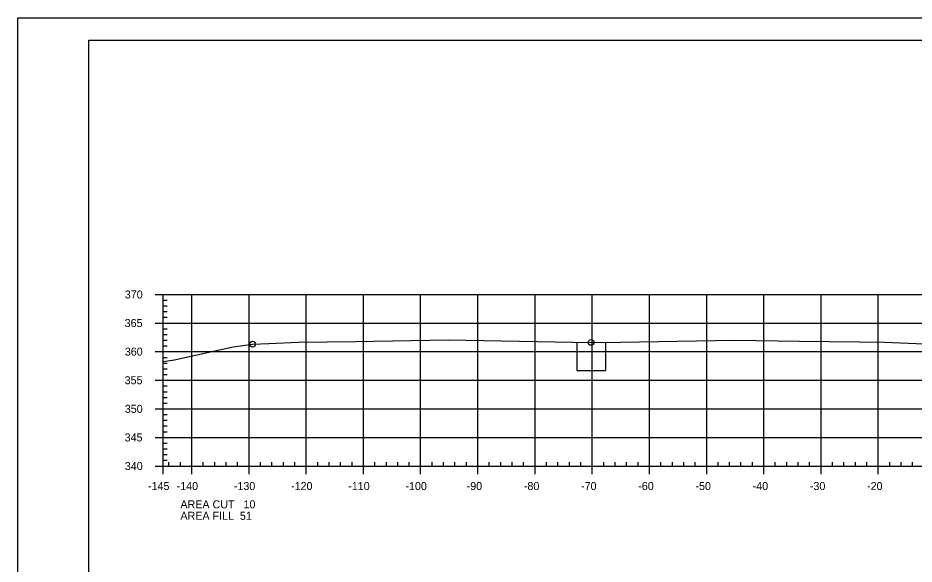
# Model space of a CAD drawing. Extents: x 1359801 to 1362404, y 372415 to 374228.
# Drawn here: x 1360417.1 to 1360573.8, y 373279.1 to 373374.6 of the extents above; entities that cross this region are included whole.
import ezdxf

# ---------------------------------------------------------------- set-up
doc = ezdxf.new("R2010")
doc.units = 0
for name, color, linetype in [('S_DRG_PT_SYM', 7, 'Continuous'), ('S_MAILBOX', 7, 'Continuous'), ('S_PRIMARY_CTL', 7, 'Continuous'), ('S_SHOULDER', 7, 'Continuous'), ('S_UTILITY_POLE_ANNOT', 7, 'Continuous'), ('S_UTL_PT_SYM', 7, 'Continuous'), ('S_WATER_UTILITIES', 7, 'Continuous')]:
    doc.layers.add(name, color=color, linetype=linetype)

msp = doc.modelspace()

# ---------------------------------------------------------------- linework, layer by layer
at = {"layer": 'S_DRG_PT_SYM'}
msp.add_lwpolyline([(1360442.53, 373314.56), (1360444.48, 373314.85), (1360449.99, 373316.06), (1360454.74, 373317.08), (1360456.47, 373317.32), (1360458.15, 373317.57), (1360460.98, 373317.68), (1360466.15, 373317.9), (1360476.17, 373318.06), (1360492.36, 373318.32), (1360514.12, 373317.93), (1360519.42, 373317.83), (1360522.47, 373317.89), (1360542.41, 373318.26), (1360553.77, 373318.1), (1360564.27, 373317.95), (1360568.61, 373317.9), (1360575.57, 373317.63)], dxfattribs=at)
at = {"layer": 'S_MAILBOX'}
for p, q in [((1360442.53, 373326.26), (1360732.53, 373326.26)), ((1360442.53, 373296.26), (1360442.53, 373326.26)), ((1360447.53, 373296.26), (1360447.53, 373326.26)), ((1360457.53, 373296.26), (1360457.53, 373326.26)), ((1360467.53, 373296.26), (1360467.53, 373326.26)), ((1360477.53, 373296.26), (1360477.53, 373326.26)), ((1360487.53, 373296.26), (1360487.53, 373326.26)), ((1360497.53, 373296.26), (1360497.53, 373326.26)), ((1360507.53, 373296.26), (1360507.53, 373326.26)), ((1360517.53, 373296.26), (1360517.53, 373326.26)), ((1360527.53, 373296.26), (1360527.53, 373326.26)), ((1360537.53, 373296.26), (1360537.53, 373326.26)), ((1360547.53, 373296.26), (1360547.53, 373326.26)), ((1360557.53, 373296.26), (1360557.53, 373326.26)), ((1360567.53, 373296.26), (1360567.53, 373326.26)), ((1360442.53, 373321.26), (1360732.53, 373321.26)), ((1360442.53, 373316.26), (1360732.53, 373316.26)), ((1360442.53, 373311.26), (1360732.53, 373311.26)), ((1360442.53, 373306.26), (1360732.53, 373306.26)), ((1360442.53, 373301.26), (1360732.53, 373301.26)), ((1360442.53, 373296.26), (1360732.53, 373296.26))]:
    msp.add_line(p, q, dxfattribs=at)
at = {"layer": 'S_SHOULDER'}
msp.add_line((1360417.13, 373374.61), (1360750.46, 373374.61), dxfattribs=at)
for points in [[(1360417.12, 373374.61), (1360750.46, 373374.61), (1360750.46, 373161.28), (1360417.12, 373161.28)], [(1360663.45, 373370.72), (1360663.45, 373360.84), (1360699.18, 373360.84), (1360699.18, 373357.92), (1360722.38, 373357.92), (1360722.38, 373333.59), (1360745.71, 373333.59), (1360745.71, 373165.26), (1360429.53, 373165.26), (1360429.53, 373370.72)]]:
    msp.add_lwpolyline(points, close=True, dxfattribs=at)
for centre in [(1360458.15, 373317.57), (1360517.32, 373317.87)]:
    msp.add_circle(centre, 0.5, dxfattribs=at)
at = {"layer": 'S_UTILITY_POLE_ANNOT'}
for p, q in [((1360514.82, 373317.87), (1360514.82, 373312.95)), ((1360519.82, 373317.87), (1360519.82, 373312.95)), ((1360514.82, 373312.95), (1360519.82, 373312.95))]:
    msp.add_line(p, q, dxfattribs=at)
at = {"layer": 'S_UTL_PT_SYM'}
for p, q in [((1360429.53, 373370.72), (1360745.71, 373370.72)), ((1360429.53, 373165.26), (1360429.53, 373370.72))]:
    msp.add_line(p, q, dxfattribs=at)
at = {"layer": 'S_WATER_UTILITIES'}
for p, q in [((1360441.13, 373326.26), (1360442.53, 373326.26)), ((1360442.53, 373296.26), (1360442.53, 373326.26)), ((1360442.53, 373325.26), (1360443.23, 373325.26)), ((1360442.53, 373324.26), (1360443.23, 373324.26)), ((1360442.53, 373323.26), (1360443.23, 373323.26)), ((1360442.53, 373322.26), (1360443.23, 373322.26)), ((1360441.13, 373321.26), (1360442.53, 373321.26)), ((1360442.53, 373320.26), (1360443.23, 373320.26)), ((1360442.53, 373319.26), (1360443.23, 373319.26)), ((1360442.53, 373318.26), (1360443.23, 373318.26)), ((1360442.53, 373317.26), (1360443.23, 373317.26)), ((1360441.13, 373316.26), (1360442.53, 373316.26)), ((1360442.53, 373315.26), (1360443.23, 373315.26)), ((1360442.53, 373314.26), (1360443.23, 373314.26)), ((1360442.53, 373313.26), (1360443.23, 373313.26)), ((1360441.13, 373311.26), (1360442.53, 373311.26)), ((1360442.53, 373312.26), (1360443.23, 373312.26)), ((1360442.53, 373310.26), (1360443.23, 373310.26)), ((1360442.53, 373309.26), (1360443.23, 373309.26)), ((1360442.53, 373308.26), (1360443.23, 373308.26)), ((1360441.13, 373306.26), (1360442.53, 373306.26)), ((1360442.53, 373307.26), (1360443.23, 373307.26)), ((1360442.53, 373305.26), (1360443.23, 373305.26)), ((1360442.53, 373304.26), (1360443.23, 373304.26)), ((1360442.53, 373303.26), (1360443.23, 373303.26)), ((1360442.53, 373302.26), (1360443.23, 373302.26)), ((1360441.13, 373301.26), (1360442.53, 373301.26)), ((1360442.53, 373300.26), (1360443.23, 373300.26)), ((1360442.53, 373299.26), (1360443.23, 373299.26)), ((1360442.53, 373298.26), (1360443.23, 373298.26)), ((1360442.53, 373297.26), (1360443.23, 373297.26)), ((1360442.53, 373296.26), (1360442.53, 373296.96)), ((1360443.53, 373296.26), (1360443.53, 373296.96)), ((1360445.53, 373296.26), (1360445.53, 373296.96)), ((1360449.53, 373296.26), (1360449.53, 373296.96)), ((1360451.53, 373296.26), (1360451.53, 373296.96)), ((1360453.53, 373296.26), (1360453.53, 373296.96)), ((1360455.53, 373296.26), (1360455.53, 373296.96)), ((1360459.53, 373296.26), (1360459.53, 373296.96)), ((1360461.53, 373296.26), (1360461.53, 373296.96)), ((1360463.53, 373296.26), (1360463.53, 373296.96)), ((1360465.53, 373296.26), (1360465.53, 373296.96)), ((1360469.53, 373296.26), (1360469.53, 373296.96)), ((1360471.53, 373296.26), (1360471.53, 373296.96)), ((1360473.53, 373296.26), (1360473.53, 373296.96)), ((1360475.53, 373296.26), (1360475.53, 373296.96)), ((1360479.53, 373296.26), (1360479.53, 373296.96)), ((1360481.53, 373296.26), (1360481.53, 373296.96)), ((1360483.53, 373296.26), (1360483.53, 373296.96)), ((1360485.53, 373296.26), (1360485.53, 373296.96)), ((1360489.53, 373296.26), (1360489.53, 373296.96)), ((1360491.53, 373296.26), (1360491.53, 373296.96)), ((1360493.53, 373296.26), (1360493.53, 373296.96)), ((1360495.53, 373296.26), (1360495.53, 373296.96)), ((1360499.53, 373296.26), (1360499.53, 373296.96)), ((1360501.53, 373296.26), (1360501.53, 373296.96)), ((1360503.53, 373296.26), (1360503.53, 373296.96)), ((1360505.53, 373296.26), (1360505.53, 373296.96)), ((1360509.53, 373296.26), (1360509.53, 373296.96)), ((1360511.53, 373296.26), (1360511.53, 373296.96)), ((1360513.53, 373296.26), (1360513.53, 373296.96)), ((1360515.53, 373296.26), (1360515.53, 373296.96)), ((1360519.53, 373296.26), (1360519.53, 373296.96)), ((1360521.53, 373296.26), (1360521.53, 373296.96)), ((1360523.53, 373296.26), (1360523.53, 373296.96)), ((1360525.53, 373296.26), (1360525.53, 373296.96)), ((1360529.53, 373296.26), (1360529.53, 373296.96)), ((1360531.53, 373296.26), (1360531.53, 373296.96)), ((1360533.53, 373296.26), (1360533.53, 373296.96)), ((1360535.53, 373296.26), (1360535.53, 373296.96)), ((1360539.53, 373296.26), (1360539.53, 373296.96)), ((1360541.53, 373296.26), (1360541.53, 373296.96)), ((1360543.53, 373296.26), (1360543.53, 373296.96)), ((1360545.53, 373296.26), (1360545.53, 373296.96)), ((1360549.53, 373296.26), (1360549.53, 373296.96)), ((1360551.53, 373296.26), (1360551.53, 373296.96)), ((1360553.53, 373296.26), (1360553.53, 373296.96)), ((1360555.53, 373296.26), (1360555.53, 373296.96)), ((1360559.53, 373296.26), (1360559.53, 373296.96)), ((1360561.53, 373296.26), (1360561.53, 373296.96)), ((1360563.53, 373296.26), (1360563.53, 373296.96)), ((1360565.53, 373296.26), (1360565.53, 373296.96)), ((1360569.53, 373296.26), (1360569.53, 373296.96)), ((1360571.53, 373296.26), (1360571.53, 373296.96)), ((1360573.53, 373296.26), (1360573.53, 373296.96)), ((1360441.13, 373296.26), (1360442.53, 373296.26)), ((1360442.53, 373296.26), (1360732.53, 373296.26)), ((1360442.53, 373294.86), (1360442.53, 373296.26)), ((1360447.53, 373294.86), (1360447.53, 373296.26)), ((1360457.53, 373294.86), (1360457.53, 373296.26)), ((1360467.53, 373294.86), (1360467.53, 373296.26)), ((1360477.53, 373294.86), (1360477.53, 373296.26)), ((1360487.53, 373294.86), (1360487.53, 373296.26)), ((1360497.53, 373294.86), (1360497.53, 373296.26)), ((1360507.53, 373294.86), (1360507.53, 373296.26)), ((1360517.53, 373294.86), (1360517.53, 373296.26)), ((1360527.53, 373294.86), (1360527.53, 373296.26)), ((1360537.53, 373294.86), (1360537.53, 373296.26)), ((1360547.53, 373294.86), (1360547.53, 373296.26)), ((1360557.53, 373294.86), (1360557.53, 373296.26)), ((1360567.53, 373294.86), (1360567.53, 373296.26))]:
    msp.add_line(p, q, dxfattribs=at)

# ---------------------------------------------------------------- texts
at = {"layer": 'S_PRIMARY_CTL'}
for s, p in [('370', (1360435.81, 373325.56)), ('365', (1360435.78, 373320.56)), ('360', (1360435.81, 373315.56)), ('355', (1360435.78, 373310.56)), ('350', (1360435.81, 373305.56)), ('345', (1360435.78, 373300.56)), ('340', (1360435.81, 373295.56)), ('-145', (1360439.86, 373292.06)), ('-140', (1360444.87, 373292.06)), ('-130', (1360454.87, 373292.06)), ('-120', (1360464.87, 373292.06)), ('-110', (1360474.87, 373292.06)), ('-100', (1360484.87, 373292.06)), ('-90', (1360495.57, 373292.06)), ('-80', (1360505.57, 373292.06)), ('-70', (1360515.57, 373292.06)), ('-60', (1360525.57, 373292.06)), ('-50', (1360535.57, 373292.06)), ('-40', (1360545.57, 373292.06)), ('-30', (1360555.57, 373292.06)), ('-20', (1360565.57, 373292.06)), ('AREA CUT   10', (1360445.53, 373288.86)), ('AREA FILL  51', (1360445.53, 373286.86))]:
    msp.add_text(s, height=1.4, dxfattribs=at).set_placement(p)
at = {"layer": 'S_SHOULDER'}
for p in [(1360466.11, 373317.85), (1360568.57, 373317.85)]:
    msp.add_text('+', height=0.1, dxfattribs=at).set_placement(p)

doc.saveas('drawing.dxf')
